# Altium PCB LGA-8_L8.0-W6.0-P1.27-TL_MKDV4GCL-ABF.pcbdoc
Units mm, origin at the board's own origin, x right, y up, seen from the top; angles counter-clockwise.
Board outline 21.29 x 18.76 mm, 2 copper layers (Top Layer, Bottom Layer), stack 0 mm thick; 1 components, 0 nets, 8 pads, 0 vias.
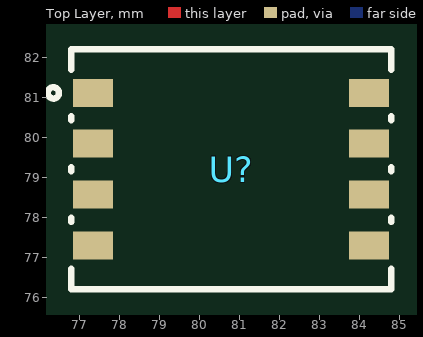
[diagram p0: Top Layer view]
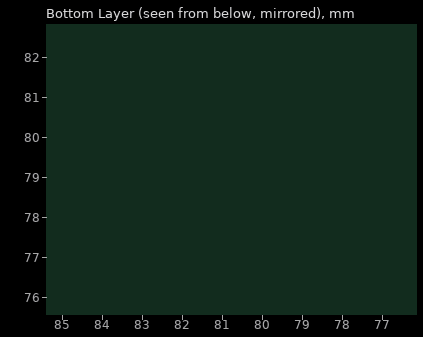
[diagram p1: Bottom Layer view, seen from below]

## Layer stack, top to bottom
Top Layer: signal copper (thickness not stored)
Bottom Layer: signal copper (thickness not stored)

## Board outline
91.136,69.85 69.85,69.85 69.85,88.61 91.136,88.61

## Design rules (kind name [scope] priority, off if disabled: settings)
PasteMaskExpansion "Paste Mask Expansion" [All] p1: expansion=0
SolderMaskExpansion "Solder Mask Expansion" [IsVia] p1: expansion=-25.4 istentingtop=TRUE
SolderMaskExpansion "Solder Mask Expansion" [All] p2: expansion=0.051 istentingtop=FALSE

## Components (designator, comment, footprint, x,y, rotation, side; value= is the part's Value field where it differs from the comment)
U? "" LGA-8_L8.0-W6.0-P1.27-TL_MKDV4GCL-ABF 80.786,79.2 r0 top

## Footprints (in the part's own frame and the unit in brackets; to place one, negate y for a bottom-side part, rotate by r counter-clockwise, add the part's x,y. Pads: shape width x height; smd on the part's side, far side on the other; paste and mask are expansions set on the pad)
LGA-8_L8.0-W6.0-P1.27-TL_MKDV4GCL-ABF [mm]
  rect 1x0.7 smd: 1(-3.45,1.905) 2(-3.45,0.635) 3(-3.45,-0.635) 4(-3.45,-1.905) 5(3.45,-1.905) 6(3.45,-0.635) 7(3.45,0.635) 8(3.45,1.905)
  silkscreen extent -4.59,-3 4,3

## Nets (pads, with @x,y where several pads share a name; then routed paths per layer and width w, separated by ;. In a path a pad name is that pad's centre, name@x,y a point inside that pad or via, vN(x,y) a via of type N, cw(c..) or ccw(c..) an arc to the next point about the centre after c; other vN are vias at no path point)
pads on no net: U?.1 U?.2 U?.3 U?.4 U?.5 U?.6 U?.7 U?.8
